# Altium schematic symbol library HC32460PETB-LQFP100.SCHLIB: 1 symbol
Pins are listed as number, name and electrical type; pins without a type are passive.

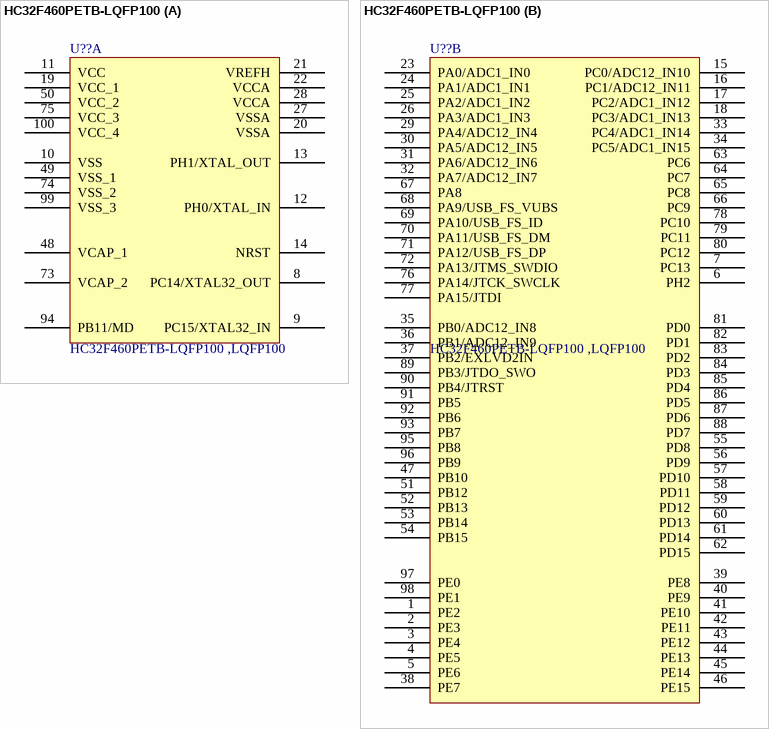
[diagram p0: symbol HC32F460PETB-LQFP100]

## HC32F460PETB-LQFP100
designator U??, comment HC32F460PETB-LQFP100 / ,LQFP100
HC32F460PETB-LQFP100 / ,LQFP100,华大HDSC; 物料代码: 08.20.00166; 名称: 集成电路; 封装: LQFP-100; 厂商: HDSC; 贴片和直插: SMT; 环保状态: RoHS2.0; PCB备注: 210219ZW; 器件优选方案: 待导入物料; 生产单位: PCS
footprint QFP50P1600X1600X160-100N
part A pins: 8 PC14/XTAL32_OUT, 9 PC15/XTAL32_IN, 10 VSS, 11 VCC, 12 PH0/XTAL_IN, 13 PH1/XTAL_OUT, 14 NRST, 19 VCC_1, 20 VSSA, 21 VREFH, 22 VCCA, 27 VSSA, 28 VCCA, 48 VCAP_1, 49 VSS_1, 50 VCC_2, 73 VCAP_2, 74 VSS_2, 75 VCC_3, 94 PB11/MD, 99 VSS_3, 100 VCC_4
part B pins: 1 PE2, 2 PE3, 3 PE4, 4 PE5, 5 PE6, 6 PH2, 7 PC13, 15 PC0/ADC12_IN10, 16 PC1/ADC12_IN11, 17 PC2/ADC1_IN12, 18 PC3/ADC1_IN13, 23 PA0/ADC1_IN0, 24 PA1/ADC1_IN1, 25 PA2/ADC1_IN2, 26 PA3/ADC1_IN3, 29 PA4/ADC12_IN4, 30 PA5/ADC12_IN5, 31 PA6/ADC12_IN6, 32 PA7/ADC12_IN7, 33 PC4/ADC1_IN14, 34 PC5/ADC1_IN15, 35 PB0/ADC12_IN8, 36 PB1/ADC12_IN9, 37 PB2/EXLVD2IN, 38 PE7, 39 PE8, 40 PE9, 41 PE10, 42 PE11, 43 PE12, 44 PE13, 45 PE14, 46 PE15, 47 PB10, 51 PB12, 52 PB13, 53 PB14, 54 PB15, 55 PD8, 56 PD9, 57 PD10, 58 PD11, 59 PD12, 60 PD13, 61 PD14, 62 PD15, 63 PC6, 64 PC7, 65 PC8, 66 PC9, 67 PA8, 68 PA9/USB_FS_VUBS, 69 PA10/USB_FS_ID, 70 PA11/USB_FS_DM, 71 PA12/USB_FS_DP, 72 PA13/JTMS_SWDIO, 76 PA14/JTCK_SWCLK, 77 PA15/JTDI, 78 PC10, 79 PC11, 80 PC12, 81 PD0, 82 PD1, 83 PD2, 84 PD3, 85 PD4, 86 PD5, 87 PD6, 88 PD7, 89 PB3/JTDO_SWO, 90 PB4/JTRST, 91 PB5, 92 PB6, 93 PB7, 95 PB8, 96 PB9, 97 PE0, 98 PE1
